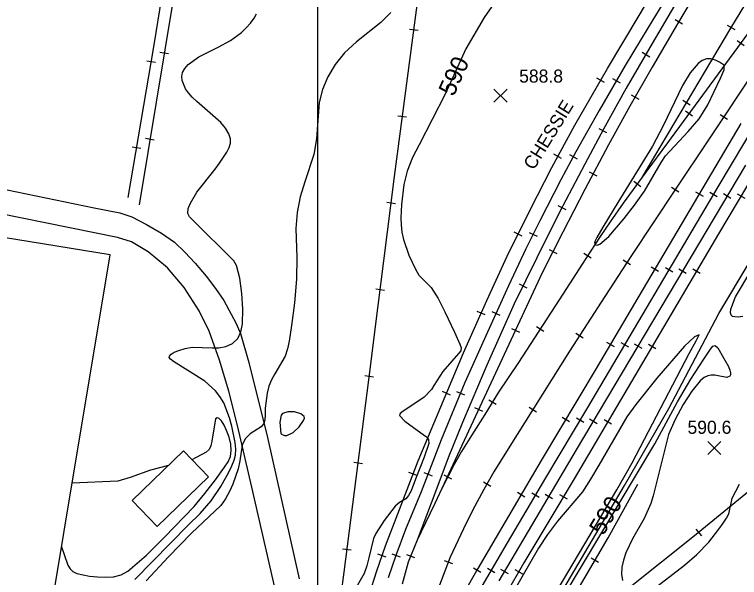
# Model space of a CAD drawing. Extents: x 79600 to 91800, y 75600 to 84400.
# Drawn here: x 87653 to 88483, y 76266 to 76910 of the extents above; entities that cross this region are included whole.
import ezdxf

# ---------------------------------------------------------------- set-up
doc = ezdxf.new("R2010")
doc.units = 0
for name, color, linetype in [('080-090$0$BLDG', 7, 'Continuous'), ('080-090$0$GRID', 7, 'Continuous'), ('080-090$0$INDEX', 7, 'Continuous'), ('080-090$0$INDXLBL', 7, 'Continuous'), ('080-090$0$INTER', 7, 'Continuous'), ('080-090$0$ROAD', 7, 'Continuous'), ('080-090$0$ROAD-NAME', 7, 'Continuous'), ('080-090$0$RR', 7, 'Continuous'), ('080-090$0$SPOTMARK', 7, 'Continuous'), ('080-090$0$SPOTS', 7, 'Continuous')]:
    doc.layers.add(name, color=color, linetype=linetype)

# ---------------------------------------------------------------- blocks, each defined once
blk = doc.blocks.new('080-090$0$SPOTS')
at = {"layer": '080-090$0$SPOTMARK'}
for p, q in [((-0.5, -0.5), (0.5, 0.5)), ((-0.5, 0.5), (0.5, -0.5))]:
    blk.add_line(p, q, dxfattribs=at)

msp = doc.modelspace()

# ---------------------------------------------------------------- linework, layer by layer
at = {"layer": '080-090$0$BLDG'}
msp.add_lwpolyline([(87656.89, 76000), (87762.62, 76635.15), (87640.39, 76655.01), (87578.87, 76283.05), (87536.55, 76288.03), (87565.24, 76474.97), (87479.74, 76489.69), (87429.04, 76190.9), (87359.93, 76202.33), (87455.64, 76795.44), (87320.19, 76816.99), (87198.34, 76070.39), (87186.96, 76000)], dxfattribs=at)
msp.add_lwpolyline([(87787.81, 76353.59), (87846.39, 76410.46), (87874.94, 76381.05), (87816.36, 76324.18)], close=True, dxfattribs=at)
at = {"layer": '080-090$0$GRID'}
msp.add_line((88000, 80000), (88000, 76000), dxfattribs=at)
at = {"layer": '080-090$0$INDEX'}
for points in [[(88199.33, 76919.22), (88190.77, 76906.99), (88169.67, 76870.92), (88146.05, 76819.08), (88116.13, 76761.09), (88108.59, 76746.4), (88102.5, 76731), (88098.63, 76715.56), (88095.88, 76692.82), (88095.18, 76677.31), (88095.48, 76669.29), (88096.43, 76661.02), (88098.2, 76652.45), (88104.21, 76634.77), (88111.85, 76618.52), (88115.72, 76611.92), (88126.44, 76601.22), (88130.06, 76597.73), (88138, 76585.15), (88145.77, 76569.84), (88156.86, 76546.58), (88162.93, 76532.95), (88164.31, 76528.61), (88164.09, 76525.2), (88143.15, 76501.55), (88133.03, 76485.29), (88130.25, 76480.78), (88121.89, 76472.14), (88103.16, 76459.48), (88097.86, 76456.05), (88094.66, 76453.43), (88093.87, 76451.11), (88099.76, 76444.73), (88122.43, 76428.35), (88125.21, 76426.25), (88127.02, 76423.43), (88127.17, 76418.86), (88121.89, 76403.32), (88112.18, 76378.22), (88106.89, 76364.86), (88104.1, 76359.58), (88101.1, 76355.8), (88093.78, 76351.31), (88088.8, 76347.17), (88076.34, 76330.89), (88066.67, 76315.81), (88063.93, 76310.33), (88058.77, 76288.14), (88056.44, 76279.04), (88053.14, 76270.26), (88041.21, 76248.86)], [(88151.9, 76000), (88159.24, 76028.12), (88165.39, 76047), (88172.5, 76065.57), (88180.5, 76082.76), (88236.55, 76176.02), (88351.11, 76371.02), (88401.87, 76459.22), (88459.36, 76567.7), (88531.11, 76687.72)]]:
    msp.add_lwpolyline(points, dxfattribs=at)
msp.add_lwpolyline([(87958.61, 76429.81), (87962.14, 76428.14), (87964.9, 76428.12), (87971.93, 76431.6), (87979.04, 76438.27), (87983.89, 76445.25), (87984.84, 76447.88), (87984.65, 76449.93), (87980.75, 76453.14), (87973.5, 76455.22), (87965.71, 76455.34), (87959.87, 76453.55), (87958.12, 76451.54), (87956.85, 76443.44), (87957.85, 76430.46)], close=True, dxfattribs=at)
at = {"layer": '080-090$0$INTER'}
for points in [[(87790.88, 76263.31), (87851.75, 76325.7), (87865.46, 76338.86), (87878.14, 76353.36), (87889.08, 76369.66), (87898.23, 76386.2), (87901.78, 76393.52), (87904.41, 76399.8), (87906, 76405.76), (87906.44, 76412.38), (87905.69, 76420.36), (87901.78, 76438.91), (87899.2, 76448.4), (87892.55, 76465.74), (87888.12, 76472.98), (87882.95, 76479.34), (87870.73, 76490.45), (87834.98, 76512.91), (87831.43, 76515.46), (87830.06, 76517.4), (87830.45, 76519.2), (87832.29, 76521.24), (87835.73, 76523.45), (87841.01, 76525.66), (87848.19, 76527.69), (87856.43, 76529.18), (87879.37, 76528.46), (87886.76, 76528.45), (87894.73, 76530.1), (87902.38, 76533.65), (87908.49, 76539.21), (87912.2, 76546.73), (87913.92, 76555.49), (87914.35, 76573.38), (87913.16, 76590.63), (87910.95, 76608.3), (87907.13, 76622.68), (87904.11, 76628.31), (87856.95, 76674.77), (87853.23, 76678.43), (87851.44, 76682.55), (87851.97, 76687.93), (87854.34, 76694.19), (87861.85, 76706.79), (87882.56, 76733.2), (87887.85, 76740.14), (87895.96, 76752.44), (87898.58, 76757.86), (87900.08, 76762.95), (87900.15, 76768.06), (87898.44, 76773.62), (87894.7, 76779.9), (87889.32, 76786.61), (87861.85, 76810.8), (87856.43, 76815.73), (87852.11, 76820.4), (87848.77, 76825.01), (87844.81, 76834.53), (87844.46, 76839.28), (87845.41, 76843.92), (87847.8, 76848.46), (87851.77, 76852.95), (87864.08, 76861.68), (87886.31, 76872.82), (87900.24, 76880.29), (87912.67, 76889.44), (87918.27, 76894.79), (87923.21, 76900.39), (87927.16, 76905.88), (87929.89, 76911.05)], [(88083.79, 76912.37), (88072.47, 76900.99), (88044.37, 76879.01), (88030.88, 76866.4), (88020.05, 76853.05), (88011.75, 76838.98), (88005.69, 76824.34), (88001.92, 76809.35), (87998.53, 76767.82), (87995.61, 76750.02), (87985.36, 76718.58), (87980.1, 76701.33), (87976.4, 76683.45), (87975.2, 76665.39), (87976.2, 76632.1), (87975.62, 76607.06), (87973.43, 76580.02), (87970.23, 76554.21), (87967.54, 76536.36), (87965.64, 76527.29), (87962.96, 76518.91), (87950.93, 76498.79), (87947.26, 76492.08), (87944.28, 76484.79), (87942.11, 76476.76), (87940.11, 76459.42), (87939.87, 76451.91), (87939.65, 76446.22), (87938.5, 76441.91), (87935.31, 76438.29), (87922.68, 76430.28), (87916.88, 76424.56), (87913.63, 76417.06), (87910.98, 76399.1), (87909.09, 76390.07), (87902.96, 76372.58), (87899.04, 76363.99), (87894.49, 76355.71), (87889.12, 76348.02), (87855.75, 76316.33), (87829.39, 76289.38), (87803.57, 76261.94)], [(88486.62, 76564.61), (88481.33, 76563.85), (88477.63, 76563.89), (88475.05, 76564.61), (88473.26, 76566.01), (88472.46, 76568.56), (88472.96, 76572.85), (88478.23, 76586.88), (88528.89, 76671.24)], [(88175.44, 76084.02), (88342.45, 76366.07), (88360.14, 76396.9), (88425.42, 76521.99), (88433.34, 76536.4), (88435.79, 76541.09), (88436.61, 76543.59), (88431.55, 76541.12), (88419.81, 76530.5), (88388.41, 76493.75), (88364.22, 76463.74), (88353.97, 76449.64), (88321.78, 76394.39), (88312.46, 76378.29), (88303.04, 76363.74), (88274.42, 76329.92), (88263.03, 76314.88), (88252.94, 76299.33), (88224.99, 76250.62)], [(88282.1, 76245.06), (88385.94, 76418.46), (88412.04, 76466.66), (88427.04, 76492.51), (88442.19, 76515.54), (88449.6, 76527.14), (88452.46, 76530.67), (88455.24, 76531.33), (88458.26, 76528.5), (88464.62, 76517.28), (88470.15, 76507.05), (88471.91, 76503.13), (88472.69, 76500.02), (88472.57, 76497.68), (88471.73, 76496.05), (88468.31, 76494.71), (88458.6, 76496.6), (88454.62, 76497.31), (88450.6, 76497.43), (88446.52, 76496.59), (88442.3, 76494.43), (88437.88, 76490.67), (88428.43, 76479.03), (88418.45, 76463.62), (88409.13, 76446.68), (88401.71, 76429.32), (88386.26, 76368.16), (88384.21, 76359.13), (88381.56, 76350.17), (88373.83, 76333), (88360.58, 76309.71), (88356.53, 76301.98), (88352.86, 76293.85), (88349.96, 76285.51), (88348.25, 76277.25), (88348, 76269.35), (88348.93, 76262.1)], [(87706.96, 76300.75), (87709.72, 76291.88), (87714.11, 76279.89), (87716.54, 76275.44), (87719.66, 76272.3), (87724.23, 76270.06), (87738.85, 76267.15), (87747.86, 76266.31), (87757.2, 76265.91), (87766.4, 76266.47), (87775.03, 76268.6), (87782.8, 76272.71), (87803.98, 76291.25), (87824.86, 76311.67), (87858.55, 76346.73), (87871.06, 76361.83), (87882.96, 76377.37), (87893.43, 76391.8), (87897.39, 76398.08), (87900.07, 76404.2), (87901.18, 76410.84), (87900.54, 76418.42), (87898.58, 76426.37), (87895.84, 76433.84), (87892.84, 76440.11), (87889.86, 76444.83), (87887.15, 76447.73), (87884.89, 76448.56), (87883.1, 76447.09), (87879.07, 76421.83), (87877.8, 76416.29), (87875.77, 76412.19), (87872.58, 76408.92), (87856.1, 76400.45)], [(87829.35, 76393.92), (87808.82, 76388.51), (87785.27, 76380.07), (87771.25, 76376.06), (87719.08, 76373.59)], [(88379.96, 76248.83), (88419.8, 76279.8), (88434.12, 76291.9), (88447.71, 76305.91), (88459.36, 76320.89), (88464.11, 76327.74), (88467.97, 76333.62), (88470.77, 76338.59), (88473.21, 76350.86), (88474.69, 76356.42), (88483.1, 76372.64)]]:
    msp.add_lwpolyline(points, dxfattribs=at)
msp.add_lwpolyline([(88463.62, 76853.53), (88460.04, 76855.7), (88455.3, 76858.03), (88450.09, 76859.52), (88445, 76859.36), (88440.12, 76857.5), (88435.44, 76854.09), (88426.54, 76843.38), (88417.83, 76829.11), (88395.51, 76782.64), (88383.5, 76759.58), (88343.65, 76694.83), (88326.3, 76666.63), (88319.6, 76655.09), (88317.72, 76651.19), (88317.07, 76648.35), (88317.78, 76646.49), (88319.84, 76645.99), (88323.22, 76647.32), (88333.2, 76655.99), (88350.77, 76676.56), (88362.73, 76691.88), (88374.23, 76707.94), (88393.4, 76740.93), (88398.35, 76748.39), (88424.01, 76776.09), (88436.63, 76790.91), (88446.52, 76806.66), (88461.13, 76837.23), (88465.2, 76846.83), (88465.56, 76852.25)], close=True, dxfattribs=at)
at = {"layer": '080-090$0$ROAD'}
for p, q in [((87542.82, 76730.16), (87744.27, 76689.01)), ((87716.27, 76665.9), (87581.92, 76693.29)), ((87744.27, 76689.01), (87773.59, 76683.2)), ((87773.59, 76683.2), (87787.16, 76678.43)), ((87787.16, 76678.43), (87804.14, 76669.82)), ((87804.14, 76669.82), (87821.36, 76659.81)), ((87770.88, 76655.07), (87716.27, 76665.9)), ((87786.96, 76650.11), (87770.88, 76655.07)), ((87821.36, 76659.81), (87836.07, 76649.44)), ((87805.82, 76638.66), (87786.96, 76650.11)), ((87836.07, 76649.44), (87847.82, 76638.02)), ((87828.02, 76620.03), (87805.82, 76638.66)), ((87847.82, 76638.02), (87859.68, 76625.61)), ((87847.07, 76597.84), (87828.02, 76620.03)), ((87859.68, 76625.61), (87872.33, 76610.54)), ((87872.33, 76610.54), (87883.05, 76596.63)), ((87864.34, 76570.8), (87847.07, 76597.84)), ((87883.05, 76596.63), (87892.51, 76582.74)), ((87892.51, 76582.74), (87900.95, 76566.93)), ((87875.83, 76547.66), (87864.34, 76570.8)), ((87900.95, 76566.93), (87906.59, 76556.61)), ((87906.59, 76556.61), (87911.78, 76545.05)), ((87887.65, 76514.47), (87875.83, 76547.66)), ((87911.78, 76545.05), (87921.23, 76511.91)), ((87898.46, 76479.06), (87887.65, 76514.47)), ((87921.23, 76511.91), (87942.5, 76425.89)), ((87908.34, 76439.76), (87898.46, 76479.06)), ((87924.64, 76368.93), (87908.34, 76439.76)), ((87942.5, 76425.89), (87978.7, 76263.9)), ((87965.01, 76194.01), (87924.64, 76368.93))]:
    msp.add_line(p, q, dxfattribs=at)
at = {"layer": '080-090$0$RR'}
for p, q in [((88497.04, 77093.16), (88378.51, 76895.37)), ((87846.16, 77081.71), (87812.58, 76875.49)), ((87851.73, 77030.65), (87795.57, 76692.48)), ((88671.8, 77018.69), (88458.85, 76659)), ((88368.21, 76909.14), (88426.06, 77007.09)), ((88576.41, 77003.21), (88400.44, 76763.15)), ((88534.42, 76997.3), (88472.7, 76894.69)), ((88087.81, 76724.69), (88115.95, 76937.17)), ((88438.05, 76943.46), (88411.96, 76899.52)), ((88594.63, 76943.22), (88458.22, 76712.75)), ((88408.65, 76920.53), (88383.13, 76876.99)), ((88331.7, 76848.26), (88368.21, 76909.14)), ((88409.17, 76904.62), (88417.77, 76899.52)), ((88378.51, 76895.37), (88351.87, 76851.72)), ((88472.7, 76894.69), (88371.17, 76723.46)), ((88411.96, 76899.52), (88383.09, 76849.92)), ((88468.89, 76898.06), (88477.46, 76892.91)), ((88114.99, 76891.82), (88105.07, 76893.14)), ((88529.7, 76890.92), (88448.13, 76767.82)), ((88480.34, 76880.61), (88488.41, 76874.7)), ((87812.58, 76875.49), (87782.91, 76700.71)), ((88383.13, 76876.99), (88353.11, 76825.74)), ((87819.51, 76867.15), (87829.37, 76865.51)), ((88371.46, 76866.96), (88380.09, 76861.91)), ((87804.43, 76857.36), (87814.29, 76855.68)), ((88294.27, 76783.63), (88331.7, 76848.26)), ((88351.87, 76851.72), (88322.27, 76800.32)), ((88383.09, 76849.92), (88357.27, 76805.41)), ((88328.34, 76832.49), (88319.69, 76837.5)), ((88337.56, 76836.89), (88346.23, 76831.9)), ((88353.11, 76825.74), (88327.24, 76779)), ((88358.87, 76818.14), (88367.52, 76813.12)), ((88417.87, 76812.02), (88426.47, 76806.92)), ((88357.27, 76805.41), (88333.12, 76761.14)), ((88322.27, 76800.32), (88295.54, 76752.9)), ((88421.22, 76799.96), (88429.28, 76794.04)), ((88460.69, 76795.82), (88469.02, 76790.3)), ((88101.86, 76792.69), (88091.95, 76794)), ((88267.93, 76735.09), (88294.27, 76783.63)), ((88327.24, 76779), (88305.7, 76738.72)), ((88322.01, 76779.83), (88330.83, 76775.11)), ((88484.53, 76785.57), (88362.89, 76579.48)), ((87803.12, 76768.5), (87812.99, 76766.86)), ((88333.12, 76761.14), (88305.76, 76709.83)), ((88400.44, 76763.15), (88375.69, 76729.64)), ((88448.13, 76767.82), (88408.87, 76709.09)), ((87787.69, 76758.77), (87797.55, 76757.1)), ((88295.54, 76752.9), (88278.23, 76720.77)), ((88279.28, 76745.53), (88270.49, 76750.29)), ((88288.18, 76749.78), (88296.98, 76745.03)), ((88305.7, 76738.72), (88276.71, 76683.82)), ((88489.62, 76737.87), (88296.11, 76411.67)), ((88243.28, 76686.65), (88267.93, 76735.09)), ((88310.94, 76730.18), (88319.76, 76725.47)), ((88375.69, 76729.64), (88349.79, 76694.21)), ((88075.77, 76628.1), (88087.81, 76724.69)), ((88278.23, 76720.77), (88254.17, 76673.99)), ((88458.22, 76712.75), (88309.04, 76460.23)), ((88361.99, 76719.37), (88370.07, 76713.47)), ((88405.23, 76712.64), (88413.54, 76707.08)), ((88305.76, 76709.83), (88280.53, 76660.98)), ((88408.87, 76709.09), (88359.22, 76634.41)), ((88432.57, 76707.38), (88441.18, 76702.29)), ((88448.91, 76706.82), (88457.52, 76701.73)), ((88464.42, 76705.21), (88473.02, 76700.1)), ((88480.32, 76705.08), (88488.92, 76699.99)), ((88088.97, 76693.56), (88079.05, 76694.8)), ((88216.98, 76633.36), (88243.28, 76686.65)), ((88275.1, 76691.48), (88283.95, 76686.82)), ((88349.79, 76694.21), (88334.94, 76672.76)), ((88276.71, 76683.82), (88250.86, 76631.63)), ((88254.17, 76673.99), (88238.52, 76641.82)), ((88334.94, 76672.76), (88323.27, 76655.99)), ((88234.02, 76656.58), (88225.05, 76661.01)), ((88242.18, 76660.76), (88251.17, 76656.39)), ((88280.53, 76660.98), (88257.04, 76614.33)), ((88323.27, 76655.99), (88306.95, 76630.96)), ((88458.85, 76659), (88325.17, 76432.24)), ((88238.52, 76641.82), (88218.61, 76599.55)), ((88264.99, 76641.23), (88273.92, 76636.73)), ((88304.9, 76636.97), (88313.28, 76631.51)), ((88193.54, 76582.8), (88216.98, 76633.36)), ((88250.86, 76631.63), (88224.86, 76579.04)), ((88306.95, 76630.96), (88280.78, 76590.08)), ((88359.22, 76634.41), (88328.6, 76587.49)), ((88349.89, 76629.27), (88358.27, 76623.81)), ((88069.21, 76577.17), (88075.77, 76628.1)), ((88381.74, 76621.26), (88390.35, 76616.18)), ((88398.05, 76620.72), (88406.66, 76615.64)), ((88257.04, 76614.33), (88141.99, 76367.42)), ((88413.4, 76619.2), (88422, 76614.1)), ((88429.45, 76618.98), (88438.06, 76613.9)), ((88076.46, 76594.33), (88066.54, 76595.61)), ((88218.61, 76599.55), (88194.28, 76546.64)), ((88230.54, 76601.82), (88239.5, 76597.38)), ((88280.78, 76590.08), (88229.79, 76511.66)), ((88328.6, 76587.49), (88288.27, 76524.74)), ((88166.82, 76522.96), (88193.54, 76582.8)), ((88224.86, 76579.04), (88193.71, 76508.55)), ((88362.89, 76579.48), (88318.82, 76505.09)), ((88058.68, 76491.99), (88069.21, 76577.17)), ((88191.62, 76566.24), (88182.49, 76570.31)), ((88199.59, 76570.17), (88208.68, 76565.99)), ((88194.28, 76546.64), (88168.58, 76488.73)), ((88221.93, 76550.82), (88230.99, 76546.6)), ((88250.67, 76552.95), (88259.05, 76547.5)), ((88295.54, 76545.3), (88303.95, 76539.89)), ((88330.84, 76535.19), (88339.44, 76530.09)), ((88347.18, 76534.62), (88355.79, 76529.54)), ((88362.38, 76533.19), (88370.98, 76528.09)), ((88378.66, 76532.83), (88387.28, 76527.75)), ((88114.96, 76399.06), (88166.82, 76522.96)), ((88288.27, 76524.74), (88247.05, 76459.08)), ((88193.71, 76508.55), (88165.76, 76443.15)), ((88229.79, 76511.66), (88207.14, 76477.97)), ((88318.82, 76505.09), (88256.07, 76399.71)), ((88064.1, 76495.12), (88054.18, 76496.35)), ((88047.9, 76408.63), (88058.68, 76491.99)), ((88168.58, 76488.73), (88141.31, 76423.18)), ((88151.98, 76474.56), (88142.76, 76478.42)), ((88158.95, 76478.6), (88168.18, 76474.76)), ((88207.14, 76477.97), (88191.22, 76452.22)), ((88195.83, 76469.2), (88204.34, 76463.94)), ((88179.69, 76460.18), (88188.76, 76455.95)), ((88247.05, 76459.08), (88217.99, 76413.11)), ((88242.15, 76460.69), (88250.61, 76455.35)), ((88309.04, 76460.23), (88260.93, 76379.65)), ((88191.22, 76452.22), (88176.17, 76428.13)), ((88279.74, 76449.24), (88288.34, 76444.13)), ((88296.26, 76448.59), (88304.85, 76443.46)), ((88311.36, 76447.19), (88319.96, 76442.09)), ((88327.88, 76446.69), (88336.5, 76441.61)), ((88165.76, 76443.15), (88149.37, 76402.49)), ((88325.17, 76432.24), (88293.56, 76378.65)), ((88141.31, 76423.18), (88118.5, 76363.53)), ((88176.17, 76428.13), (88164.74, 76409.96)), ((88217.99, 76413.11), (88201.76, 76386.4)), ((88030.23, 76271.7), (88047.9, 76408.63)), ((88164.74, 76409.96), (88156.18, 76394.94)), ((88296.11, 76411.67), (88207.25, 76261.79)), ((88051.3, 76395.92), (88041.39, 76397.2)), ((88091.85, 76338.58), (88114.96, 76399.06)), ((88149.37, 76402.49), (88135.14, 76364.84)), ((88256.07, 76399.71), (88204.31, 76311.82)), ((88156.18, 76394.94), (88141.99, 76367.42)), ((88113.9, 76382.28), (88104.56, 76385.84)), ((88121.62, 76385.69), (88130.96, 76382.11)), ((88144.41, 76383.03), (88153.3, 76378.45)), ((88201.76, 76386.4), (88190.44, 76366.41)), ((88260.93, 76379.65), (88217.14, 76305.11)), ((88513.13, 76380.5), (88431.4, 76313.23)), ((88189.72, 76375.28), (88198.42, 76370.35)), ((88293.56, 76378.65), (88265.74, 76332.09)), ((88332.54, 76311.08), (88366.41, 76372.3)), ((88118.5, 76363.53), (88100.67, 76320.52)), ((88135.14, 76364.84), (88113.79, 76308.23)), ((88141.99, 76367.42), (88133.97, 76350.15)), ((88190.44, 76366.41), (88177.35, 76342.28)), ((88228.76, 76363.19), (88237.37, 76358.12)), ((88245.12, 76362.61), (88253.74, 76357.55)), ((88260.36, 76361.17), (88268.96, 76356.07)), ((88276.98, 76360.65), (88285.56, 76355.52)), ((88133.97, 76350.15), (88123.47, 76328.25)), ((88077.64, 76301.77), (88091.85, 76338.58)), ((88177.35, 76342.28), (88166.98, 76321.43)), ((88265.74, 76332.09), (88236.18, 76282.5)), ((88123.47, 76328.25), (88113.79, 76308.23)), ((88166.98, 76321.43), (88151.89, 76288.97)), ((88100.67, 76320.52), (88089.69, 76290.9)), ((88431.4, 76313.23), (88357.95, 76254.56)), ((88432.92, 76320.96), (88439.28, 76313.24)), ((88113.79, 76308.23), (88103.61, 76283.34)), ((88217.14, 76305.11), (88182.63, 76246.7)), ((88204.31, 76311.82), (88183.56, 76275.99)), ((88281.65, 76224.42), (88332.54, 76311.08)), ((88038.5, 76296.74), (88028.58, 76298.02)), ((88067.95, 76273.38), (88077.64, 76301.77)), ((88078.54, 76288.93), (88069.08, 76292.17)), ((88089.69, 76290.9), (88080.61, 76265.28)), ((88084.96, 76292.53), (88094.39, 76289.19)), ((88101.8, 76292.12), (88111.06, 76288.34)), ((88151.89, 76288.97), (88125.69, 76221.02)), ((88103.61, 76283.34), (88096.63, 76257.95)), ((88145.02, 76285.07), (88154.36, 76281.48)), ((88236.18, 76282.5), (88214.12, 76244.05)), ((88321.64, 76282.65), (88313.02, 76287.71)), ((88022.17, 76210.19), (88030.23, 76271.7)), ((88058.66, 76244.55), (88067.95, 76273.38)), ((88183.56, 76275.99), (88156.85, 76229.41)), ((88178.26, 76276.81), (88186.94, 76271.83)), ((88194.4, 76276.45), (88203.01, 76271.36)), ((88209.36, 76275.15), (88217.96, 76270.05)), ((88225.87, 76274.59), (88234.54, 76269.62))]:
    msp.add_line(p, q, dxfattribs=at)

# ---------------------------------------------------------------- block references
at = {"layer": '080-090$0$SPOTMARK', "xscale": 15, "yscale": 15}
for p in [(88209.34, 76817.23), (88454.12, 76413.8)]:
    msp.add_blockref('080-090$0$SPOTS', p, dxfattribs=at)

# ---------------------------------------------------------------- texts
at = {"layer": '080-090$0$INDXLBL'}
for rotation, p in [(65.53724, (88155.65, 76815.45)), (59.29027, (88326.77, 76312.44))]:
    msp.add_text('590', height=20, rotation=rotation, dxfattribs=at).set_placement(p)
at = {"layer": '080-090$0$ROAD-NAME'}
msp.add_text('CHESSIE', height=15, rotation=58.28127, dxfattribs=at).set_placement((88247.41, 76731.23))
at = {"layer": '080-090$0$SPOTS'}
for s, p in [('588.8', (88230.69, 76832.23)), ('590.6', (88423.4, 76430.11))]:
    msp.add_text(s, height=15, dxfattribs=at).set_placement(p)

doc.saveas('drawing.dxf')
